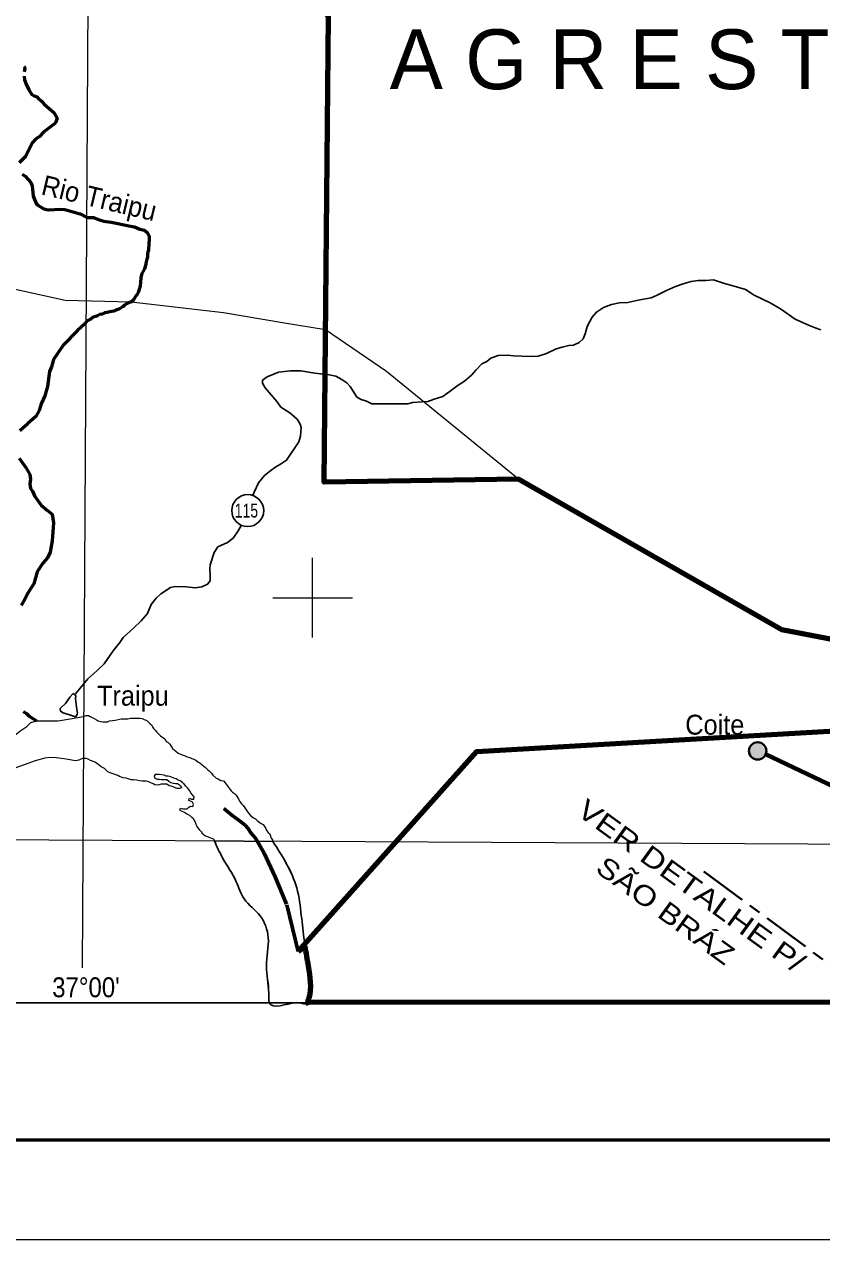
# Model space of a CAD drawing. Extents: x 553962 to 842807, y 8883888 to 9032388.
# Drawn here: x 717768 to 737772, y 8883888 to 8914394 of the extents above; entities that cross this region are included whole.
import ezdxf
from ezdxf.enums import TextEntityAlignment as Align

# ---------------------------------------------------------------- set-up
doc = ezdxf.new("R2010")
doc.units = 0
doc.header["$LTSCALE"] = 200
doc.linetypes.add('LONG_DASH_SHORT_DASH', pattern=[9.9, 6, -1.2, 1.5, -1.2])
for name, color, linetype, lineweight in [('1', 7, 'Continuous', 13), ('12', 7, 'Continuous', 25), ('2', 7, 'Continuous', 13), ('21', 7, 'Continuous', 25), ('24', 7, 'Continuous', 25), ('25', 7, 'Continuous', 13), ('28', 7, 'Continuous', 40), ('3', 7, 'Continuous', 13), ('41', 7, 'Continuous', 40), ('48', 7, 'Continuous', 25), ('57', 7, 'Continuous', 13), ('7', 7, 'LONG_DASH_SHORT_DASH', 60), ('9', 7, 'Continuous', 90)]:
    doc.layers.add(name, color=color, linetype=linetype, lineweight=lineweight)
for name, color, linetype in [('13', 7, 'Continuous'), ('46', 7, 'Continuous'), ('49', 7, 'Continuous')]:
    doc.layers.add(name, color=color, linetype=linetype)

msp = doc.modelspace()

# ---------------------------------------------------------------- hatches: boundary and pattern name
at = {"layer": '41'}
msp.add_hatch(color=256, dxfattribs=at).paths.add_polyline_path([(736385.1, 8896156.5, 1), (735947.5, 8896156.5, 1)])

# ---------------------------------------------------------------- linework, layer by layer
at = {"layer": '1'}
for points in [[(719978.9, 9023574.5), (719561.6, 8949232.2), (719215.6, 8890710.6)], [(564751.7, 8894587.5), (664411.9, 8894209.9), (791388.5, 8893536.2)]]:
    msp.add_lwpolyline(points, dxfattribs=at)
at = {"layer": '12'}
for points in [[(732698.6, 8907406), (732912.6, 8907415.8), (733208.3, 8907476.3), (733493.7, 8907526.8), (733646.8, 8907597.8), (733881.6, 8907714.5), (734106.1, 8907810.9), (734320.4, 8907892), (734498.8, 8907937.5), (734677.2, 8907962.7), (734865.7, 8907967.4), (735054.3, 8907977.3), (735334.1, 8907885.1), (735578.4, 8907823.5), (735863.4, 8907741.4), (736076.8, 8907598.4), (736483.7, 8907404.1), (736742.9, 8907255.9), (737103.6, 8906990.3), (737439.3, 8906842), (737612.3, 8906775.4), (737750.2, 8906727.3)], [(727039.6, 8904864.2), (727284.1, 8904868.9), (727391.1, 8904868.7), (727508.4, 8904899), (727747.9, 8904919), (727890.6, 8904928.9), (728048.7, 8904984.6), (728268, 8905055.5), (728451.9, 8905187.7), (728651.2, 8905340.1), (728809.4, 8905436.6), (728993.4, 8905594.2), (729095.8, 8905716.2), (729249.1, 8905868.8), (729371.7, 8905934.8), (729473.8, 8906011), (729657.5, 8906082), (729896.9, 8906091.7), (730039.5, 8906071.1), (730253.5, 8906065.6), (730497.9, 8906055), (730661, 8906064.9), (730870.1, 8906130.7), (731110, 8906247.4), (731263, 8906293), (731426.1, 8906328.3), (731543.3, 8906338.3), (731686.2, 8906409.4), (731788.5, 8906500.9), (731839.8, 8906623.1), (731891.5, 8906806.3), (731958.2, 8906938.7), (732014.6, 8907040.4), (732122.1, 8907172.7), (732300.8, 8907289.5), (732499.7, 8907365.6), (732698.6, 8907406)], [(723502.8, 8902567), (723531.6, 8902649.7), (723639.5, 8902883.8), (723793, 8903072), (723920.7, 8903168.5), (724079.1, 8903290.5), (724191.4, 8903356.5), (724349.7, 8903453), (724652, 8903916), (724698.3, 8904058.6), (724714.4, 8904272.5), (724689.2, 8904354.1), (724613.3, 8904481.5), (724430.5, 8904644.9), (724201.8, 8904787.9), (724110.5, 8904915.5), (723811.3, 8905272.6), (723745.5, 8905389.9), (723740.7, 8905461.2), (723858.1, 8905542.5), (724143.8, 8905659.1), (724444.6, 8905699.3), (724704.4, 8905698.9), (725060.7, 8905637.1), (725417.2, 8905595.7), (725585.2, 8905564.8), (725732.6, 8905477.9), (725859.7, 8905396.2), (725945.9, 8905304.3), (726062.4, 8905115.6), (726113.1, 8905039.1), (726219.8, 8904977.8), (726352.1, 8904931.7), (726489.4, 8904870.3), (726601.5, 8904865), (727039.6, 8904864.2)], [(719051.7, 8897586.9), (719362.5, 8897965.7), (719587.4, 8898163.9), (719771.5, 8898341.9), (719996.8, 8898667.5), (720160.6, 8898881.1), (720247.7, 8899003.2), (720508.3, 8899237.1), (720697.5, 8899420.1), (720856.1, 8899608.3), (720953.7, 8899827.2), (721076.6, 8899989.9), (721194.2, 8900101.8), (721434.2, 8900254.2), (721551.4, 8900279.4), (721826.5, 8900273.8), (722050.5, 8900248), (722223.9, 8900278.2), (722366.7, 8900339.1), (722428.2, 8900425.6), (722433.7, 8900552.9), (722424.2, 8900726.1), (722429.7, 8900828), (722532.7, 8901133.4), (722624.9, 8901275.9), (722864.7, 8901387.5), (723007.8, 8901494.2), (723130.7, 8901677.4), (723197.4, 8901799.6), (723209.3, 8901823.1)]]:
    msp.add_lwpolyline(points, dxfattribs=at)
at = {"layer": '2'}
for p, q in [((725000, 8899000), (725000, 8901000)), ((724000, 8900000), (726000, 8900000))]:
    msp.add_line(p, q, dxfattribs=at)
at = {"layer": '21'}
msp.add_lwpolyline([(718993.1, 8897599.9), (719057.4, 8897544.6), (719055.9, 8897461.4), (719085.3, 8897192.5), (719103.1, 8897108.8), (719098.1, 8897076.1), (719079.4, 8897033), (719065.5, 8897020), (719028.2, 8897020.1), (718974.7, 8897034.1), (718746.2, 8897111.7), (718679.7, 8897153.1), (718671.6, 8897221.2), (718685, 8897240.1), (718799.2, 8897348.2), (718862.4, 8897430.9), (718906.6, 8897502.9)], close=True, dxfattribs=at)
at = {"layer": '24', "lineweight": 53}
for points in [[(717753.4, 8913338.3), (717771.3, 8913315.3), (717779.7, 8913284.7), (717767.4, 8913198.7)], [(717765.2, 8913088.6), (717776, 8913003.3), (717816.4, 8912891.5), (717881.6, 8912752), (717959.7, 8912633.8), (718012.2, 8912595.1), (718103.9, 8912566), (718108.4, 8912552.9), (718200.6, 8912462.7), (718263.8, 8912388), (718510.9, 8912180.7), (718595.9, 8912042.5), (718559.6, 8911942), (718525.1, 8911895.3), (718256.7, 8911695.7), (718139.8, 8911569.1), (718058.8, 8911518.2), (717971, 8911425.9), (717799.8, 8911079.5), (717637.2, 8910919.9)], [(717717.9, 8910632.5), (717786.1, 8910583.9), (717932.5, 8910426.1), (717961.9, 8910338.5), (717987.1, 8910076.6), (718063.3, 8909892.7), (718110.2, 8909851.7), (718240.9, 8909774.5), (718323.8, 8909744.9), (718380.9, 8909735.3), (718665.9, 8909753.1), (718783.6, 8909747.4), (719169.5, 8909639.4), (719326.4, 8909556.3)], [(719326.4, 8909556.3), (719371.3, 8909542.5), (719371.3, 8909542.5), (719504.5, 8909548.1), (719504.5, 8909548.1), (719504.5, 8909548.1), (719626.5, 8909498.2)], [(719626.5, 8909498.2), (719765.2, 8909453.8), (719765.2, 8909453.8), (719765.2, 8909453.8), (719765.2, 8909453.8), (719948.4, 8909426.1), (719948.4, 8909426.1), (719948.4, 8909426.1), (720114.8, 8909398.4), (720114.8, 8909398.4), (720114.8, 8909398.4), (720392.3, 8909337.4), (720392.3, 8909337.4), (720392.3, 8909337.4), (720392.3, 8909337.4), (720531, 8909309.6), (720531, 8909309.6), (720531, 8909309.6), (720664.2, 8909248.6), (720780.7, 8909226.5), (720848.9, 8909167.8), (720879.1, 8909126.9), (720899.1, 8909075.8), (720898.7, 8909024.9), (720898.3, 8908963.8), (720892.8, 8908897.6), (720892.3, 8908831.3), (720886.9, 8908780.4), (720886.5, 8908724.4), (720865.8, 8908678.7), (720860.4, 8908622.7), (720854.9, 8908561.6), (720844.3, 8908500.6), (720828.6, 8908434.4), (720818, 8908383.6), (720797.2, 8908307.3), (720781.6, 8908256.4), (720750.7, 8908200.6), (720714.6, 8908139.7), (720699, 8908078.7), (720693.5, 8908027.8), (720680.1, 8907917.9)], [(720680.1, 8907917.9), (720671.8, 8907819.1), (720661.2, 8907768.2), (720640.5, 8907712.3), (720624.9, 8907661.5), (720594, 8907605.6), (720558.1, 8907560), (720532.3, 8907509.3), (720496.4, 8907468.7), (720460.5, 8907428.2), (720409.6, 8907413.3), (720363.7, 8907393.2), (720312.7, 8907373.1), (720276.8, 8907337.7), (720241, 8907302.3), (720179.7, 8907267), (720118.4, 8907231.8), (720062.3, 8907216.8), (720016.4, 8907196.8), (719965.5, 8907181.8), (719909.5, 8907177.1), (719843.3, 8907162.2), (719792.3, 8907152.3), (719720.9, 8907122.2), (719664.9, 8907107.3), (719603.6, 8907077.1), (719552.6, 8907057.1), (719496.6, 8907042.2), (719445.4, 8907001.8), (719343.4, 8906951.5), (719283.6, 8906877)], [(719283.6, 8906877), (719100.8, 8906711), (718751.9, 8906345.6), (718502.7, 8905980.3), (718452.8, 8905797.7), (718403, 8905681.4), (718353.1, 8905299.5), (718286.7, 8905067), (718187, 8904867.8), (718137.2, 8904701.7), (718054.1, 8904552.2), (717859.9, 8904374.3), (717854.7, 8904369.6)], [(717854.7, 8904369.6), (717655.3, 8904186.9)], [(717638.7, 8903506.1), (717804.9, 8903273.6), (717904.6, 8903091), (717921.2, 8902974.7), (717904.6, 8902858.5), (717921.2, 8902742.3), (717971.1, 8902675.9), (718020.9, 8902559.6), (718187, 8902327.1), (718353.2, 8902194.3), (718469.5, 8902094.7), (718502.7, 8901878.8), (718469.5, 8901430.4), (718419.6, 8901148.2), (718353.2, 8900998.7), (718236.8, 8900865.9), (718087.3, 8900650), (718004.2, 8900351.1), (717937.8, 8900251.5), (717854.7, 8900118.6), (717771.7, 8899952.6), (717688.6, 8899803.1)], [(717738.4, 8897146.3), (717821.5, 8897096.4), (717888, 8897030), (718070.7, 8896913.8)]]:
    msp.add_lwpolyline(points, dxfattribs=at)
at = {"layer": '25', "lineweight": 25}
msp.add_line((724002.8, 8893886.5), (722537.3, 8893896.5), dxfattribs=at)
msp.add_line((724002.8, 8893886.5), (722537.3, 8893896.5), dxfattribs=at)
at = {"layer": '25'}
for points in [[(716671.9, 8896141.4), (716736, 8896160), (716876.8, 8896172.9), (716996.8, 8896216.3), (717443.2, 8896481.3), (717658.9, 8896651.8), (717833.2, 8896772.8), (717934, 8896865.6), (718070.7, 8896913.8), (718220.3, 8896913.8), (718619, 8896913.8), (718918.1, 8896963.6), (719252.2, 8897020.3)], [(719252.2, 8897020.3), (719320.1, 8897049.2), (719376, 8897048.8), (719416.5, 8897018), (719467.2, 8896997.3), (719517.9, 8896971.5), (719578.7, 8896940.5), (719624.3, 8896914.8), (719680.1, 8896894), (719736.1, 8896888.6), (719797.1, 8896883.1), (719858.1, 8896887.8), (719909.1, 8896907.8), (719980.4, 8896922.7), (720046.6, 8896927.3), (720199.4, 8896962), (720255.3, 8896961.7), (720306.2, 8896961.3), (720362.2, 8896961), (720428.4, 8896980.9), (720479.3, 8896980.6), (720540.3, 8896980.2), (720606.4, 8896979.8), (720667.5, 8896979.4), (720723.3, 8896968.8), (720779.1, 8896948.1), (720845, 8896917.1), (720880.4, 8896881.2), (720920.8, 8896845.3), (720956.2, 8896809.4)], [(720956.2, 8896809.4), (720981.3, 8896763.4), (721006.4, 8896717.4), (721046.8, 8896676.4), (721082.2, 8896635.4), (721127.7, 8896594.4), (721188.3, 8896538), (721289.5, 8896455.8), (721329.8, 8896404.6), (721375.3, 8896368.7), (721420.8, 8896322.5), (721461, 8896261.2), (721486.2, 8896215.2), (721567.1, 8896148.4), (721627.8, 8896097.1), (721683.5, 8896071.3), (721749.5, 8896050.5), (721805.3, 8896034.8), (721856, 8896009), (721916.9, 8895988.3), (721972.7, 8895967.5), (722018.4, 8895946.9), (722069, 8895921.1), (722119.7, 8895885.1), (722175.4, 8895854.2), (722231, 8895808), (722271.5, 8895772), (722312, 8895741.2), (722367.5, 8895689.9), (722402.9, 8895654), (722463.5, 8895597.6), (722493.7, 8895546.5), (722584.8, 8895474.6), (722635.5, 8895453.9), (722701.4, 8895417.8), (722762.3, 8895402.1), (722802.7, 8895366.2), (722832.9, 8895320.2), (722873.2, 8895263.9), (722923.6, 8895197.3), (722953.8, 8895151.3), (722994.3, 8895120.5), (723039.9, 8895089.6), (723085.4, 8895048.6), (723145.7, 8894951.4), (723165.7, 8894895.3), (723221.1, 8894818.5), (723261.6, 8894782.6), (723301.9, 8894726.3), (723337.1, 8894675.1), (723367.3, 8894624), (723402.6, 8894583), (723453.1, 8894526.7), (723518.8, 8894475.3), (723564.4, 8894449.5), (723609.9, 8894408.5), (723655.5, 8894372.5), (723706.1, 8894336.6), (723761.8, 8894305.6), (723797.1, 8894259.6), (723827.3, 8894208.4), (723842.2, 8894157.4), (723887.6, 8894111.3), (723928.1, 8894075.3), (723948, 8894019.2)], [(719242.1, 8895974.6), (719137.8, 8895926.7), (719051.9, 8895910.8), (718819, 8895950.7), (718570.6, 8895982.3), (718406.7, 8895992.1), (718284.1, 8895976.8), (718038.4, 8895905.8), (717250.7, 8895623.3), (716998.4, 8895554.6), (716915, 8895518.1), (716881.8, 8895513.8)], [(721516.7, 8895476.3), (721445.7, 8895507.4), (721379.7, 8895523.1), (721323.7, 8895523.4), (721273, 8895544.1), (721222.2, 8895559.7), (721151.1, 8895560.2), (721054.4, 8895560.8), (721023.6, 8895520.3), (721043.6, 8895469.2), (721104.5, 8895443.3), (721160.4, 8895443), (721211.3, 8895442.7), (721277.4, 8895442.2), (721343.5, 8895436.7), (721394.1, 8895395.6), (721444.7, 8895364.7), (721505.6, 8895344), (721561.5, 8895338.5), (721612.4, 8895338.2), (721688.3, 8895286.8), (721708.2, 8895225.5), (721657.3, 8895210.6), (721606.4, 8895210.9), (721555.7, 8895231.6), (721499.9, 8895252.3), (721454.2, 8895273), (721398.3, 8895278.4), (721342.7, 8895319.6), (721276.6, 8895325.1), (721205.3, 8895320.4), (721154.4, 8895305.5), (721098.4, 8895300.7), (721042.5, 8895301.1), (720996.9, 8895326.9), (720941.1, 8895357.8), (720890.4, 8895378.5), (720824.4, 8895399.3), (720773.6, 8895399.6), (720722.7, 8895399.9), (720656.6, 8895405.4), (720580.4, 8895421.2), (720509.3, 8895426.8), (720448.2, 8895427.2), (720397.5, 8895447.9), (720326.5, 8895468.7), (720250.3, 8895484.5), (720158.9, 8895515.6), (720113.3, 8895541.4), (720062.6, 8895557), (719996.6, 8895577.8), (719920.5, 8895608.8), (719864.8, 8895634.7), (719819.3, 8895675.7), (719778.8, 8895711.6), (719692.7, 8895758), (719647.2, 8895799.1), (719606.7, 8895829.9), (719535.8, 8895876.2), (719480.1, 8895902), (719429.3, 8895917.6), (719373.6, 8895948.5), (719317.8, 8895969.3), (719266.9, 8895969.6), (719242.1, 8895974.6)], [(722073.4, 8894336.8), (722053.4, 8894382.8), (722013.2, 8894449.3), (721972.7, 8894485.2), (721917.1, 8894531.4), (721846.2, 8894572.6), (721770.2, 8894618.9), (721724.6, 8894639.6), (721673.9, 8894665.4), (721689.5, 8894716.2), (721745.3, 8894700.6), (721801.3, 8894700.2), (721852.2, 8894705), (721893.1, 8894740.4), (721934, 8894770.7), (721995, 8894765.2), (722010.6, 8894821.2), (721985.5, 8894867.2), (721934.8, 8894893), (721889.3, 8894923.8), (721909.9, 8894969.5), (721960.6, 8894943.7), (722021.6, 8894943.3), (722027.1, 8895004.4), (721986.8, 8895050.5), (721946.5, 8895106.8), (721911.2, 8895163.1), (721871, 8895219.4), (721825.5, 8895260.4), (721780.1, 8895321.8), (721719.4, 8895368.1), (721679, 8895409.1), (721628.2, 8895424.7), (721577.6, 8895455.6), (721516.7, 8895476.3)], [(722537.3, 8893896.5), (722543.5, 8893916.1), (722503.1, 8893952.1), (722447.2, 8893962.6), (722401.6, 8893983.3), (722350.9, 8894004), (722295.1, 8894024.7), (722244.5, 8894065.8), (722214.3, 8894122), (722174, 8894168.1), (722128.6, 8894224.4), (722098.4, 8894270.5), (722073.4, 8894336.8)], [(723948, 8894019.2), (723962.9, 8893968.2), (723993.2, 8893927.2), (724002.8, 8893886.5), (722537.3, 8893896.5)]]:
    msp.add_lwpolyline(points, dxfattribs=at)
at = {"layer": '25', "lineweight": 25}
for points in [[(722537.3, 8893896.5), (722740.6, 8893475.5), (723084.4, 8892873.8), (723285, 8892444), (723686.1, 8892014.3), (723886.7, 8891469.9), (723843.7, 8890753.6), (723901, 8890080.3), (723900.8, 8889934.8), (723915.3, 8889836.7), (724574.3, 8889836.7), (724631.6, 8889836.7), (724883.2, 8889836.5), (724893.2, 8889883.7), (724911.8, 8889958.1), (724898, 8890758.3), (724794.3, 8891380.3), (724717.6, 8892028.6), (724603, 8892716.2), (724002.8, 8893886.5)], [(722537.3, 8893896.5), (722740.6, 8893475.5), (723084.4, 8892873.8), (723285, 8892444), (723686.1, 8892014.3), (723886.7, 8891469.9), (723843.7, 8890753.6), (723901, 8890080.3), (723901.3, 8889998.4)], [(724811.6, 8891262.3), (724794.3, 8891380.3), (724717.6, 8892028.6), (724603, 8892716.2), (724002.8, 8893886.5)]]:
    msp.add_spline(points, degree=3, dxfattribs=at)
at = {"layer": '28', "lineweight": 80}
msp.add_line((736369.7, 8896074.3), (739990, 8894349.3), dxfattribs=at)
at = {"layer": '28', "linetype": 'LONG_DASH_SHORT_DASH'}
msp.add_line((738961.9, 8890066.1), (734805.2, 8893139.2), dxfattribs=at)
at = {"layer": '3'}
msp.add_lwpolyline([(842807.3, 9032387.8), (842807.3, 8883887.8), (553961.7, 8883887.8), (553961.7, 9032387.8)], close=True, dxfattribs=at)
at = {"layer": '3', "lineweight": 53}
msp.add_lwpolyline([(840307.3, 9029887.8), (840307.3, 8886387.8), (560211.7, 8886387.8), (560211.7, 9029887.8)], close=True, dxfattribs=at)
at = {"layer": '3', "lineweight": 25}
msp.add_lwpolyline([(563033.9, 9026438.8), (793061.1, 9026438.8), (793495.6, 8889836.8), (563468.3, 8889836.8)], close=True, dxfattribs=at)
at = {"layer": '41'}
msp.add_circle((736166.3, 8896156.5), 218.8, dxfattribs=at)
at = {"layer": '48'}
msp.add_circle((723371.8, 8902188.1), 401.3, dxfattribs=at)
at = {"layer": '57', "lineweight": 90}
msp.add_line((724813.3, 8891251.4), (724638.9, 8891123.6), dxfattribs=at)
at = {"layer": '57', "lineweight": 25}
for points in [[(793292.6, 8953646.3), (793495.6, 8889836.8), (724892.6, 8889849.6)], [(724638.9, 8891123.6), (729122.2, 8896139.1), (740717.5, 8896813.6), (741371.9, 8898310.2)]]:
    msp.add_lwpolyline(points, dxfattribs=at)
at = {"layer": '57'}
for points in [[(725327.2, 8906726.4), (724297.2, 8906891.3), (722767.2, 8907153.7), (720450.5, 8907416.1), (718789.4, 8907459.9), (716210.4, 8908028.4), (715117.6, 8908509.5), (713325.3, 8909602.9), (711708, 8910958.7), (710877.4, 8912095.8), (710134.6, 8913345.1), (709242.2, 8913071.2)], [(724804.4, 8891308.7), (729122.2, 8896139.1), (740717.5, 8896813.6), (741371.9, 8898310.2), (736775.3, 8899194.4), (730163.4, 8902976.8), (726857.8, 8905680.8), (725327.2, 8906726.4)], [(716671.9, 8896141.4), (716736, 8896160), (716876.8, 8896172.9), (716996.8, 8896216.3), (717443.2, 8896481.3), (717658.9, 8896651.8), (717833.2, 8896772.8), (717934, 8896865.6), (718070.7, 8896913.8), (718220.3, 8896913.8), (718619, 8896913.8), (718918.1, 8896963.6), (719252.2, 8897020.3)], [(719252.2, 8897020.3), (719320.1, 8897049.2), (719376, 8897048.8), (719416.5, 8897018), (719467.2, 8896997.3), (719517.9, 8896971.5), (719578.7, 8896940.5), (719624.3, 8896914.8), (719680.1, 8896894), (719736.1, 8896888.6), (719797.1, 8896883.1), (719858.1, 8896887.8), (719909.1, 8896907.8), (719980.4, 8896922.7), (720046.6, 8896927.3), (720199.4, 8896962), (720255.3, 8896961.7), (720306.2, 8896961.3), (720362.2, 8896961), (720428.4, 8896980.9), (720479.3, 8896980.6), (720540.3, 8896980.2), (720606.4, 8896979.8), (720667.5, 8896979.4), (720723.3, 8896968.8), (720779.1, 8896948.1), (720845, 8896917.1), (720880.4, 8896881.2), (720920.8, 8896845.3), (720956.2, 8896809.4)], [(720956.2, 8896809.4), (720981.3, 8896763.4), (721006.4, 8896717.4), (721046.8, 8896676.4), (721082.2, 8896635.4), (721127.7, 8896594.4), (721188.3, 8896538), (721289.5, 8896455.8), (721329.8, 8896404.6), (721375.3, 8896368.7), (721420.8, 8896322.5), (721461, 8896261.2), (721486.2, 8896215.2), (721567.1, 8896148.4), (721627.8, 8896097.1), (721683.5, 8896071.3), (721749.5, 8896050.5), (721805.3, 8896034.8), (721856, 8896009), (721916.9, 8895988.3), (721972.7, 8895967.5), (722018.4, 8895946.9), (722069, 8895921.1), (722119.7, 8895885.1), (722175.4, 8895854.2), (722231, 8895808), (722271.5, 8895772), (722312, 8895741.2), (722367.5, 8895689.9), (722402.9, 8895654), (722463.5, 8895597.6), (722493.7, 8895546.5), (722584.8, 8895474.6), (722635.5, 8895453.9), (722701.4, 8895417.8), (722762.3, 8895402.1), (722802.7, 8895366.2), (722832.9, 8895320.2), (722873.2, 8895263.9), (722923.6, 8895197.3), (722953.8, 8895151.3), (722994.3, 8895120.5), (723039.9, 8895089.6), (723085.4, 8895048.6), (723145.7, 8894951.4), (723165.7, 8894895.3), (723221.1, 8894818.5), (723261.6, 8894782.6), (723301.9, 8894726.3), (723337.1, 8894675.1), (723367.3, 8894624), (723402.6, 8894583), (723453.1, 8894526.7), (723518.8, 8894475.3), (723564.4, 8894449.5), (723609.9, 8894408.5), (723655.5, 8894372.5), (723706.1, 8894336.6), (723761.8, 8894305.6), (723797.1, 8894259.6), (723827.3, 8894208.4), (723842.2, 8894157.4), (723887.6, 8894111.3), (723928.1, 8894075.3), (723948, 8894019.2)], [(723948, 8894019.2), (723962.9, 8893968.2), (723993.2, 8893927.2), (724002.8, 8893886.5)]]:
    msp.add_lwpolyline(points, dxfattribs=at)
at = {"layer": '57', "lineweight": 90}
for points in [[(724638.9, 8891123.6), (729122.2, 8896139.1), (740717.5, 8896813.6), (741371.9, 8898310.2)], [(775519.3, 8889840.2), (724892.6, 8889849.6), (724839.1, 8889834.1)]]:
    msp.add_lwpolyline(points, dxfattribs=at)
at = {"layer": '57'}
msp.add_spline([(724002.8, 8893886.5), (724603, 8892716.2), (724717.6, 8892028.6), (724794.3, 8891380.3), (724804.4, 8891308.7)], degree=3, dxfattribs=at)
at = {"layer": '57', "lineweight": 25}
msp.add_spline([(724839.1, 8889834.1), (724883.2, 8889836.5), (724893.2, 8889883.7), (724911.8, 8889958.1), (724898, 8890758.3), (724813.3, 8891251.4)], degree=3, dxfattribs=at)
at = {"layer": '57', "lineweight": 90}
msp.add_spline([(724839.1, 8889834.1), (724883.2, 8889836.5), (724893.2, 8889883.7), (724911.8, 8889958.1), (724898, 8890758.3), (724813.3, 8891251.4)], degree=3, dxfattribs=at)
at = {"layer": '7'}
msp.add_lwpolyline([(724638.9, 8891123.6), (724349.6, 8892305.9), (724059.6, 8892992.2), (723788.9, 8893591.5), (723566.6, 8893968.5), (723450.6, 8894103.8), (723373.3, 8894219.2), (723307.3, 8894290.7), (723154.9, 8894408.1), (722972, 8894546), (722773.8, 8894710.7)], dxfattribs=at)
at = {"layer": '9'}
msp.add_line((741371.9, 8898310.2), (736775.3, 8899194.4), dxfattribs=at)
for points in [[(741371.9, 8898310.2), (736775.3, 8899194.4), (730163.4, 8902976.8), (725291.2, 8902898), (725401.2, 8914588.3), (719613.1, 8922670.1)], [(724638.9, 8891123.6), (729122.2, 8896139.1), (740717.5, 8896813.6), (741371.9, 8898310.2)]]:
    msp.add_lwpolyline(points, dxfattribs=at)

# ---------------------------------------------------------------- texts
at = {"layer": '13'}
msp.add_text('A G R E S T E', height=1500, dxfattribs=at).set_placement((733397.9, 8912766.7), align=Align.CENTER)
at = {"layer": '28'}
for s, width, p in [('VER DETALHE P/', 1.25, (731592.8, 8894575.1)), ('SÃO BRÁZ', 1.2, (732065.4, 8893140.1))]:
    msp.add_text(s, height=500, rotation=323.968, dxfattribs=dict(at, width=width)).set_placement(p)
at = {"layer": '41', "width": 0.95}
for s, p in [('Traipu', (719591.1, 8897292.6)), ('Coite', (734349.7, 8896564.3))]:
    msp.add_text(s, height=500, dxfattribs=at).set_placement(p)
at = {"layer": '46', "width": 0.9}
msp.add_text("37°00'", height=500, dxfattribs=at).set_placement((719315, 8889973.1), align=Align.CENTER)
at = {"layer": '48', "width": 0.75}
msp.add_text('115', height=350, dxfattribs=at).set_placement((723340.2, 8902014.7), align=Align.CENTER)
at = {"layer": '49', "width": 0.95}
msp.add_text('Rio Traipu', height=500, rotation=346.601, dxfattribs=at).set_placement((719591, 8909789.6), align=Align.CENTER)

doc.saveas('drawing.dxf')
